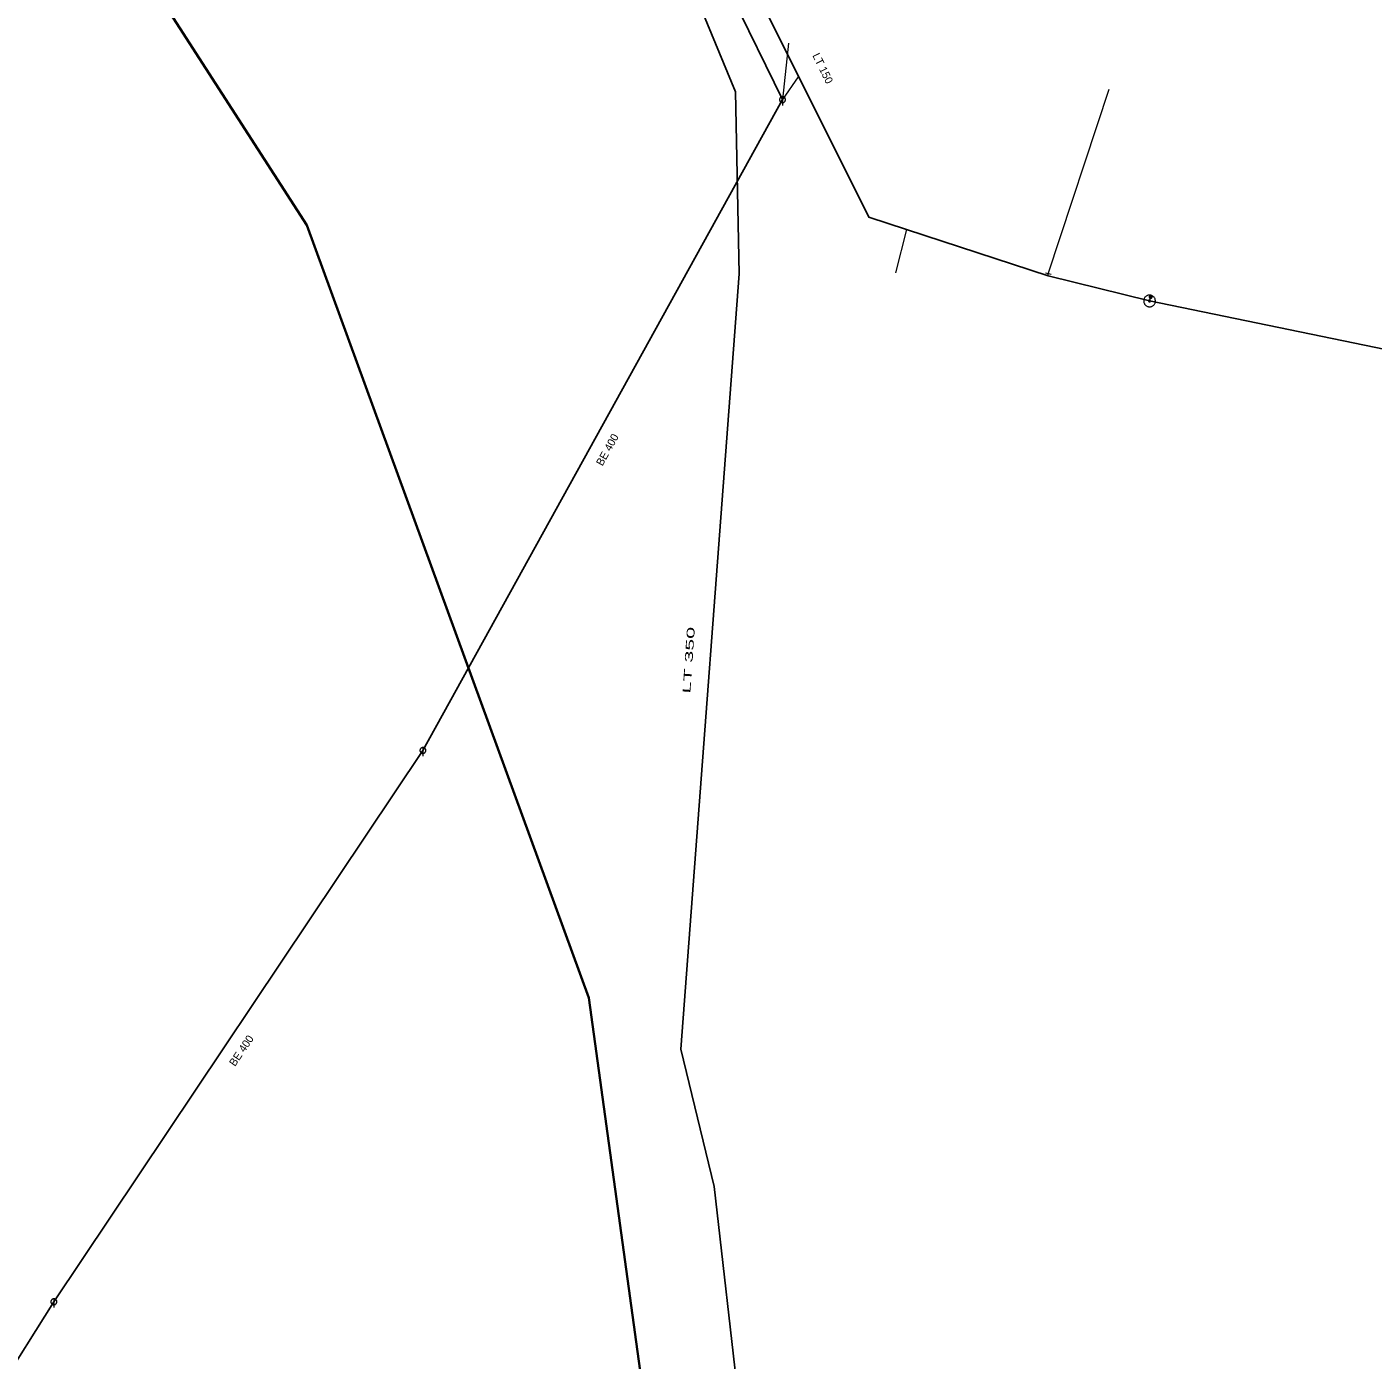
# Model space of a CAD drawing. Extents: x -687468 to -685917, y -974192 to -973456.
# Drawn here: x -686146.9 to -686032, y -973743.3 to -973629.5 of the extents above; entities that cross this region are included whole.
import ezdxf
from ezdxf.enums import TextEntityAlignment as Align

# ---------------------------------------------------------------- set-up
doc = ezdxf.new("R2010")
doc.units = 0
doc.header["$LTSCALE"] = 0.27
for name, color, linetype, lineweight in [('1', 7, 'Continuous', 13), ('11', 7, 'Continuous', 13), ('13', 7, 'Continuous', 13), ('14', 7, 'Continuous', 25), ('17', 7, 'Continuous', 25), ('22', 7, 'Continuous', 13), ('34', 7, 'Continuous', 13), ('47', 7, 'Continuous', 13), ('9', 7, 'Continuous', 13)]:
    doc.layers.add(name, color=color, linetype=linetype, lineweight=lineweight)

msp = doc.modelspace()

# ---------------------------------------------------------------- linework, layer by layer
at = {"layer": '11'}
for p in [(-686081.876, -973630.858), (-686081.043, -973633.743)]:
    msp.add_line(p, (-686082.39, -973635.68), dxfattribs=at)
at = {"layer": '13'}
for p, q in [((-686059.708, -973650.548), (-686054.519, -973634.795)), ((-686071.797, -973646.764), (-686072.73, -973650.474))]:
    msp.add_line(p, q, dxfattribs=at)
at = {"layer": '14'}
for p, q in [((-686098.62, -973602.51), (-686082.39, -973635.68)), ((-686082.39, -973635.68), (-686113.079, -973691.236)), ((-686113.079, -973691.236), (-686144.579, -973738.3)), ((-686144.579, -973738.3), (-686176.51, -973788.84))]:
    msp.add_line(p, q, dxfattribs=at)
at = {"layer": '14', "lineweight": 13}
for p, q in [((-686059.705, -973650.715), (-686059.708, -973650.548)), ((-686051.061, -973652.866), (-686050.965, -973652.512))]:
    msp.add_line(p, q, dxfattribs=at)
at = {"layer": '17', "lineweight": 35}
msp.add_lwpolyline([(-686160.425, -973551.891), (-686169.469, -973574.282), (-686122.999, -973646.384), (-686098.932, -973712.353), (-686089.329, -973782.048), (-686297.791, -974027.806), (-686326.807, -974076.614), (-686379.703, -974100.561), (-686411.584, -974111.413)], dxfattribs=at)
at = {"layer": '17'}
for points in [[(-686051.061, -973652.866), (-686059.705, -973650.715), (-686071.797, -973646.764), (-686075.022, -973645.71), (-686084.908, -973625.859)], [(-686089.459, -973627.585), (-686086.411, -973635.017), (-686086.079, -973650.552), (-686091.072, -973716.745), (-686088.221, -973728.447), (-686086.081, -973747.168), (-686087.506, -973758.201), (-686097.397, -973770.949)], [(-685917.086, -973739.927), (-685925.488, -973736.036), (-685936.592, -973728.633), (-685945.129, -973721.528), (-685963.855, -973704.352), (-685983.197, -973675.239), (-685998.767, -973663.649), (-686051.061, -973652.866)]]:
    msp.add_lwpolyline(points, dxfattribs=at)
at = {"layer": '22'}
for p, q in [((-686082.389, -973635.428), (-686082.39, -973636.172)), ((-686113.079, -973690.984), (-686113.08, -973691.728)), ((-686144.578, -973738.048), (-686144.579, -973738.792))]:
    msp.add_line(p, q, dxfattribs=at)
for points in [[(-686082.138, -973635.68), (-686082.139, -973635.654), (-686082.143, -973635.628), (-686082.149, -973635.602), (-686082.159, -973635.578), (-686082.171, -973635.554), (-686082.185, -973635.532), (-686082.202, -973635.511), (-686082.22, -973635.493), (-686082.241, -973635.476), (-686082.263, -973635.462), (-686082.287, -973635.45), (-686082.311, -973635.44), (-686082.337, -973635.434), (-686082.363, -973635.43), (-686082.389, -973635.428), (-686082.415, -973635.429), (-686082.441, -973635.433), (-686082.467, -973635.439), (-686082.492, -973635.449), (-686082.515, -973635.461), (-686082.537, -973635.475), (-686082.558, -973635.492), (-686082.576, -973635.51), (-686082.593, -973635.531), (-686082.607, -973635.553), (-686082.619, -973635.577), (-686082.629, -973635.601), (-686082.636, -973635.627), (-686082.64, -973635.653), (-686082.642, -973635.679), (-686082.641, -973635.705), (-686082.637, -973635.731), (-686082.63, -973635.757), (-686082.62, -973635.782), (-686082.608, -973635.805), (-686082.594, -973635.827), (-686082.577, -973635.848), (-686082.559, -973635.866), (-686082.538, -973635.883), (-686082.516, -973635.897), (-686082.493, -973635.909), (-686082.468, -973635.919), (-686082.442, -973635.926), (-686082.416, -973635.93), (-686082.39, -973635.932), (-686082.364, -973635.931), (-686082.338, -973635.927), (-686082.312, -973635.92), (-686082.288, -973635.91), (-686082.264, -973635.898), (-686082.242, -973635.884), (-686082.221, -973635.867), (-686082.203, -973635.849), (-686082.186, -973635.828), (-686082.172, -973635.806), (-686082.16, -973635.783), (-686082.15, -973635.758), (-686082.144, -973635.732), (-686082.14, -973635.706)], [(-686112.828, -973691.236), (-686112.829, -973691.21), (-686112.833, -973691.184), (-686112.839, -973691.158), (-686112.849, -973691.134), (-686112.861, -973691.11), (-686112.875, -973691.088), (-686112.892, -973691.067), (-686112.91, -973691.049), (-686112.931, -973691.032), (-686112.953, -973691.018), (-686112.977, -973691.006), (-686113.001, -973690.996), (-686113.027, -973690.99), (-686113.053, -973690.986), (-686113.079, -973690.984), (-686113.105, -973690.985), (-686113.131, -973690.989), (-686113.157, -973690.995), (-686113.182, -973691.005), (-686113.205, -973691.017), (-686113.227, -973691.031), (-686113.248, -973691.048), (-686113.266, -973691.066), (-686113.283, -973691.087), (-686113.297, -973691.109), (-686113.309, -973691.133), (-686113.319, -973691.157), (-686113.326, -973691.183), (-686113.33, -973691.209), (-686113.331, -973691.235), (-686113.331, -973691.261), (-686113.327, -973691.287), (-686113.32, -973691.313), (-686113.31, -973691.338), (-686113.298, -973691.361), (-686113.284, -973691.383), (-686113.267, -973691.404), (-686113.249, -973691.422), (-686113.228, -973691.439), (-686113.206, -973691.453), (-686113.183, -973691.465), (-686113.158, -973691.475), (-686113.132, -973691.482), (-686113.106, -973691.486), (-686113.08, -973691.488), (-686113.054, -973691.487), (-686113.028, -973691.483), (-686113.002, -973691.476), (-686112.978, -973691.466), (-686112.954, -973691.454), (-686112.932, -973691.44), (-686112.911, -973691.423), (-686112.893, -973691.405), (-686112.876, -973691.384), (-686112.862, -973691.362), (-686112.85, -973691.339), (-686112.84, -973691.314), (-686112.834, -973691.288), (-686112.83, -973691.262)], [(-686144.327, -973738.3), (-686144.328, -973738.274), (-686144.332, -973738.248), (-686144.338, -973738.222), (-686144.348, -973738.198), (-686144.36, -973738.174), (-686144.374, -973738.152), (-686144.391, -973738.131), (-686144.409, -973738.113), (-686144.43, -973738.096), (-686144.452, -973738.082), (-686144.476, -973738.07), (-686144.5, -973738.06), (-686144.526, -973738.054), (-686144.552, -973738.05), (-686144.578, -973738.048), (-686144.604, -973738.049), (-686144.63, -973738.053), (-686144.656, -973738.059), (-686144.681, -973738.069), (-686144.704, -973738.081), (-686144.726, -973738.095), (-686144.747, -973738.112), (-686144.765, -973738.13), (-686144.782, -973738.151), (-686144.796, -973738.173), (-686144.808, -973738.197), (-686144.818, -973738.221), (-686144.825, -973738.247), (-686144.829, -973738.273), (-686144.831, -973738.299), (-686144.83, -973738.325), (-686144.826, -973738.351), (-686144.819, -973738.377), (-686144.809, -973738.402), (-686144.797, -973738.425), (-686144.783, -973738.447), (-686144.766, -973738.468), (-686144.748, -973738.486), (-686144.727, -973738.503), (-686144.705, -973738.517), (-686144.682, -973738.529), (-686144.657, -973738.539), (-686144.631, -973738.546), (-686144.605, -973738.55), (-686144.579, -973738.552), (-686144.553, -973738.551), (-686144.527, -973738.547), (-686144.501, -973738.54), (-686144.477, -973738.53), (-686144.453, -973738.518), (-686144.431, -973738.504), (-686144.41, -973738.487), (-686144.392, -973738.469), (-686144.375, -973738.448), (-686144.361, -973738.426), (-686144.349, -973738.403), (-686144.339, -973738.378), (-686144.333, -973738.352), (-686144.329, -973738.326)]]:
    msp.add_lwpolyline(points, close=True, dxfattribs=at)
at = {"layer": '34'}
msp.add_line((-686059.466, -973650.604), (-686059.949, -973650.491), dxfattribs=at)
at = {"layer": '47'}
for points in [[(-686050.577, -973652.992), (-686050.567, -973652.941), (-686050.561, -973652.889), (-686050.562, -973652.837), (-686050.567, -973652.785), (-686050.578, -973652.733), (-686050.595, -973652.683), (-686050.617, -973652.636), (-686050.643, -973652.591), (-686050.674, -973652.549), (-686050.709, -973652.51), (-686050.748, -973652.475), (-686050.791, -973652.445), (-686050.836, -973652.419), (-686050.884, -973652.398), (-686050.934, -973652.382), (-686050.985, -973652.372), (-686051.037, -973652.366), (-686051.09, -973652.367), (-686051.141, -973652.372), (-686051.193, -973652.383), (-686051.243, -973652.4), (-686051.291, -973652.422), (-686051.336, -973652.448), (-686051.378, -973652.478), (-686051.416, -973652.514), (-686051.451, -973652.553), (-686051.482, -973652.596), (-686051.507, -973652.641), (-686051.528, -973652.689), (-686051.544, -973652.739), (-686051.554, -973652.79), (-686051.56, -973652.842), (-686051.56, -973652.895), (-686051.554, -973652.946), (-686051.543, -973652.998), (-686051.527, -973653.047), (-686051.505, -973653.095), (-686051.479, -973653.14), (-686051.448, -973653.183), (-686051.412, -973653.221), (-686051.373, -973653.256), (-686051.331, -973653.287), (-686051.285, -973653.312), (-686051.237, -973653.333), (-686051.187, -973653.349), (-686051.136, -973653.359), (-686051.084, -973653.365), (-686051.032, -973653.365), (-686050.98, -973653.359), (-686050.928, -973653.348), (-686050.879, -973653.332), (-686050.832, -973653.31), (-686050.787, -973653.284), (-686050.744, -973653.252), (-686050.705, -973653.217), (-686050.67, -973653.178), (-686050.64, -973653.136), (-686050.614, -973653.09), (-686050.593, -973653.042)], [(-686050.981, -973652.886), (-686050.979, -973652.878), (-686050.979, -973652.869), (-686050.979, -973652.861), (-686050.98, -973652.853), (-686050.981, -973652.844), (-686050.984, -973652.836), (-686050.988, -973652.828), (-686050.992, -973652.82), (-686050.997, -973652.814), (-686051.003, -973652.807), (-686051.01, -973652.801), (-686051.017, -973652.796), (-686051.024, -973652.792), (-686051.031, -973652.788), (-686051.04, -973652.786), (-686051.048, -973652.784), (-686051.057, -973652.784), (-686051.065, -973652.784), (-686051.073, -973652.785), (-686051.082, -973652.786), (-686051.09, -973652.789), (-686051.098, -973652.793), (-686051.106, -973652.797), (-686051.113, -973652.802), (-686051.119, -973652.808), (-686051.125, -973652.815), (-686051.13, -973652.822), (-686051.134, -973652.829), (-686051.138, -973652.836), (-686051.14, -973652.845), (-686051.142, -973652.853), (-686051.142, -973652.862), (-686051.142, -973652.87), (-686051.141, -973652.878), (-686051.14, -973652.887), (-686051.137, -973652.895), (-686051.133, -973652.903), (-686051.129, -973652.911), (-686051.124, -973652.918), (-686051.118, -973652.924), (-686051.111, -973652.93), (-686051.104, -973652.935), (-686051.097, -973652.939), (-686051.09, -973652.943), (-686051.081, -973652.945), (-686051.073, -973652.947), (-686051.064, -973652.947), (-686051.056, -973652.947), (-686051.048, -973652.946), (-686051.039, -973652.945), (-686051.031, -973652.942), (-686051.023, -973652.938), (-686051.015, -973652.934), (-686051.009, -973652.929), (-686051.002, -973652.923), (-686050.996, -973652.916), (-686050.991, -973652.909), (-686050.987, -973652.902), (-686050.983, -973652.895)]]:
    msp.add_lwpolyline(points, close=True, dxfattribs=at)
at = {"layer": '9'}
for points in [[(-686050.838, -973652.512), (-686050.84, -973652.499), (-686050.842, -973652.486), (-686050.845, -973652.473), (-686050.85, -973652.461), (-686050.855, -973652.449), (-686050.863, -973652.438), (-686050.87, -973652.428), (-686050.88, -973652.418), (-686050.891, -973652.41), (-686050.902, -973652.402), (-686050.914, -973652.397), (-686050.926, -973652.392), (-686050.939, -973652.389), (-686050.951, -973652.387), (-686050.965, -973652.386), (-686050.978, -973652.387), (-686050.99, -973652.389), (-686051.004, -973652.392), (-686051.016, -973652.397), (-686051.027, -973652.402), (-686051.039, -973652.41), (-686051.049, -973652.418), (-686051.059, -973652.428), (-686051.066, -973652.438), (-686051.074, -973652.449), (-686051.08, -973652.461), (-686051.085, -973652.473), (-686051.088, -973652.486), (-686051.09, -973652.499), (-686051.091, -973652.512), (-686051.09, -973652.525), (-686051.088, -973652.538), (-686051.085, -973652.551), (-686051.08, -973652.563), (-686051.074, -973652.575), (-686051.066, -973652.586), (-686051.059, -973652.596), (-686051.049, -973652.606), (-686051.039, -973652.614), (-686051.027, -973652.621), (-686051.016, -973652.627), (-686051.004, -973652.632), (-686050.99, -973652.635), (-686050.978, -973652.637), (-686050.965, -973652.638), (-686050.951, -973652.637), (-686050.939, -973652.635), (-686050.926, -973652.632), (-686050.914, -973652.627), (-686050.902, -973652.621), (-686050.891, -973652.614), (-686050.88, -973652.606), (-686050.87, -973652.596), (-686050.863, -973652.586), (-686050.855, -973652.575), (-686050.85, -973652.563), (-686050.845, -973652.551), (-686050.842, -973652.538), (-686050.84, -973652.525)], [(-686050.858, -973652.512), (-686050.858, -973652.5), (-686050.86, -973652.49), (-686050.864, -973652.478), (-686050.868, -973652.469), (-686050.873, -973652.459), (-686050.879, -973652.45), (-686050.886, -973652.441), (-686050.894, -973652.433), (-686050.902, -973652.426), (-686050.912, -973652.42), (-686050.922, -973652.415), (-686050.931, -973652.411), (-686050.943, -973652.407), (-686050.953, -973652.406), (-686050.965, -973652.406), (-686050.976, -973652.406), (-686050.987, -973652.407), (-686050.998, -973652.411), (-686051.007, -973652.415), (-686051.017, -973652.42), (-686051.027, -973652.426), (-686051.036, -973652.433), (-686051.044, -973652.441), (-686051.051, -973652.45), (-686051.056, -973652.459), (-686051.061, -973652.469), (-686051.066, -973652.478), (-686051.069, -973652.49), (-686051.071, -973652.5), (-686051.071, -973652.512), (-686051.071, -973652.523), (-686051.069, -973652.534), (-686051.066, -973652.545), (-686051.061, -973652.554), (-686051.056, -973652.565), (-686051.051, -973652.574), (-686051.044, -973652.583), (-686051.036, -973652.591), (-686051.027, -973652.598), (-686051.017, -973652.603), (-686051.007, -973652.608), (-686050.998, -973652.613), (-686050.987, -973652.616), (-686050.976, -973652.618), (-686050.965, -973652.618), (-686050.953, -973652.618), (-686050.943, -973652.616), (-686050.931, -973652.613), (-686050.922, -973652.608), (-686050.912, -973652.603), (-686050.902, -973652.598), (-686050.894, -973652.591), (-686050.886, -973652.583), (-686050.879, -973652.574), (-686050.873, -973652.565), (-686050.868, -973652.554), (-686050.864, -973652.545), (-686050.86, -973652.534), (-686050.858, -973652.523)], [(-686050.877, -973652.512), (-686050.879, -973652.503), (-686050.88, -973652.494), (-686050.882, -973652.485), (-686050.886, -973652.477), (-686050.89, -973652.469), (-686050.895, -973652.461), (-686050.901, -973652.454), (-686050.907, -973652.448), (-686050.914, -973652.442), (-686050.922, -973652.437), (-686050.929, -973652.433), (-686050.938, -973652.429), (-686050.946, -973652.427), (-686050.956, -973652.426), (-686050.965, -973652.424), (-686050.973, -973652.426), (-686050.983, -973652.427), (-686050.992, -973652.429), (-686051, -973652.433), (-686051.007, -973652.437), (-686051.016, -973652.442), (-686051.022, -973652.448), (-686051.029, -973652.454), (-686051.034, -973652.461), (-686051.039, -973652.469), (-686051.044, -973652.477), (-686051.047, -973652.485), (-686051.049, -973652.494), (-686051.051, -973652.503), (-686051.052, -973652.512), (-686051.051, -973652.521), (-686051.049, -973652.53), (-686051.047, -973652.539), (-686051.044, -973652.547), (-686051.039, -973652.554), (-686051.034, -973652.563), (-686051.029, -973652.57), (-686051.022, -973652.576), (-686051.016, -973652.581), (-686051.007, -973652.587), (-686051, -973652.591), (-686050.992, -973652.594), (-686050.983, -973652.597), (-686050.973, -973652.598), (-686050.965, -973652.599), (-686050.956, -973652.598), (-686050.946, -973652.597), (-686050.938, -973652.594), (-686050.929, -973652.591), (-686050.922, -973652.587), (-686050.914, -973652.581), (-686050.907, -973652.576), (-686050.901, -973652.57), (-686050.895, -973652.563), (-686050.89, -973652.554), (-686050.886, -973652.547), (-686050.882, -973652.539), (-686050.88, -973652.53), (-686050.879, -973652.521)], [(-686050.897, -973652.512), (-686050.897, -973652.505), (-686050.9, -973652.498), (-686050.901, -973652.491), (-686050.904, -973652.485), (-686050.907, -973652.478), (-686050.911, -973652.473), (-686050.914, -973652.467), (-686050.919, -973652.462), (-686050.926, -973652.458), (-686050.931, -973652.454), (-686050.938, -973652.451), (-686050.944, -973652.448), (-686050.951, -973652.447), (-686050.958, -973652.445), (-686050.965, -973652.445), (-686050.972, -973652.445), (-686050.978, -973652.447), (-686050.985, -973652.448), (-686050.992, -973652.451), (-686050.999, -973652.454), (-686051.004, -973652.458), (-686051.01, -973652.462), (-686051.015, -973652.467), (-686051.019, -973652.473), (-686051.022, -973652.478), (-686051.026, -973652.485), (-686051.029, -973652.491), (-686051.031, -973652.498), (-686051.032, -973652.505), (-686051.032, -973652.512), (-686051.032, -973652.519), (-686051.031, -973652.526), (-686051.029, -973652.532), (-686051.026, -973652.539), (-686051.022, -973652.546), (-686051.019, -973652.551), (-686051.015, -973652.557), (-686051.01, -973652.562), (-686051.004, -973652.566), (-686050.999, -973652.57), (-686050.992, -973652.573), (-686050.985, -973652.576), (-686050.978, -973652.578), (-686050.972, -973652.579), (-686050.965, -973652.579), (-686050.958, -973652.579), (-686050.951, -973652.578), (-686050.944, -973652.576), (-686050.938, -973652.573), (-686050.931, -973652.57), (-686050.926, -973652.566), (-686050.919, -973652.562), (-686050.914, -973652.557), (-686050.911, -973652.551), (-686050.907, -973652.546), (-686050.904, -973652.539), (-686050.901, -973652.532), (-686050.9, -973652.526), (-686050.897, -973652.519)], [(-686050.918, -973652.512), (-686050.918, -973652.507), (-686050.919, -973652.502), (-686050.919, -973652.497), (-686050.922, -973652.493), (-686050.924, -973652.488), (-686050.927, -973652.483), (-686050.929, -973652.481), (-686050.934, -973652.477), (-686050.936, -973652.474), (-686050.941, -973652.471), (-686050.946, -973652.469), (-686050.95, -973652.467), (-686050.955, -973652.466), (-686050.96, -973652.465), (-686050.965, -973652.465), (-686050.97, -973652.465), (-686050.975, -973652.466), (-686050.98, -973652.467), (-686050.983, -973652.469), (-686050.989, -973652.471), (-686050.993, -973652.474), (-686050.997, -973652.477), (-686051, -973652.481), (-686051.002, -973652.483), (-686051.005, -973652.488), (-686051.007, -973652.493), (-686051.01, -973652.497), (-686051.011, -973652.502), (-686051.012, -973652.507), (-686051.012, -973652.512), (-686051.012, -973652.517), (-686051.011, -973652.522), (-686051.01, -973652.527), (-686051.007, -973652.531), (-686051.005, -973652.536), (-686051.002, -973652.54), (-686051, -973652.544), (-686050.997, -973652.547), (-686050.993, -973652.549), (-686050.989, -973652.553), (-686050.983, -973652.554), (-686050.98, -973652.557), (-686050.975, -973652.558), (-686050.97, -973652.559), (-686050.965, -973652.559), (-686050.96, -973652.559), (-686050.955, -973652.558), (-686050.95, -973652.557), (-686050.946, -973652.554), (-686050.941, -973652.553), (-686050.936, -973652.549), (-686050.934, -973652.547), (-686050.929, -973652.544), (-686050.927, -973652.54), (-686050.924, -973652.536), (-686050.922, -973652.531), (-686050.919, -973652.527), (-686050.919, -973652.522), (-686050.918, -973652.517)], [(-686050.938, -973652.512), (-686050.938, -973652.509), (-686050.938, -973652.505), (-686050.939, -973652.504), (-686050.94, -973652.5), (-686050.941, -973652.498), (-686050.943, -973652.496), (-686050.945, -973652.494), (-686050.946, -973652.492), (-686050.949, -973652.49), (-686050.951, -973652.488), (-686050.953, -973652.487), (-686050.956, -973652.486), (-686050.958, -973652.485), (-686050.962, -973652.485), (-686050.965, -973652.485), (-686050.968, -973652.485), (-686050.971, -973652.485), (-686050.973, -973652.486), (-686050.976, -973652.487), (-686050.978, -973652.488), (-686050.98, -973652.49), (-686050.983, -973652.492), (-686050.985, -973652.494), (-686050.987, -973652.496), (-686050.989, -973652.498), (-686050.99, -973652.5), (-686050.99, -973652.504), (-686050.992, -973652.505), (-686050.992, -973652.509), (-686050.993, -973652.512), (-686050.992, -973652.515), (-686050.992, -973652.518), (-686050.99, -973652.521), (-686050.99, -973652.523), (-686050.989, -973652.526), (-686050.987, -973652.527), (-686050.985, -973652.531), (-686050.983, -973652.532), (-686050.98, -973652.534), (-686050.978, -973652.536), (-686050.976, -973652.537), (-686050.973, -973652.538), (-686050.971, -973652.539), (-686050.968, -973652.539), (-686050.965, -973652.54), (-686050.962, -973652.539), (-686050.958, -973652.539), (-686050.956, -973652.538), (-686050.953, -973652.537), (-686050.951, -973652.536), (-686050.949, -973652.534), (-686050.946, -973652.532), (-686050.945, -973652.531), (-686050.943, -973652.527), (-686050.941, -973652.526), (-686050.94, -973652.523), (-686050.939, -973652.521), (-686050.938, -973652.518), (-686050.938, -973652.515)], [(-686050.956, -973652.512), (-686050.956, -973652.511), (-686050.956, -973652.51), (-686050.958, -973652.51), (-686050.958, -973652.509), (-686050.958, -973652.508), (-686050.958, -973652.507), (-686050.958, -973652.507), (-686050.96, -973652.505), (-686050.96, -973652.505), (-686050.961, -973652.505), (-686050.962, -973652.505), (-686050.963, -973652.505), (-686050.963, -973652.504), (-686050.963, -973652.504), (-686050.965, -973652.504), (-686050.966, -973652.504), (-686050.967, -973652.504), (-686050.967, -973652.505), (-686050.968, -973652.505), (-686050.968, -973652.505), (-686050.97, -973652.505), (-686050.97, -973652.505), (-686050.971, -973652.507), (-686050.971, -973652.507), (-686050.972, -973652.508), (-686050.972, -973652.509), (-686050.973, -973652.51), (-686050.973, -973652.51), (-686050.973, -973652.511), (-686050.973, -973652.512), (-686050.973, -973652.513), (-686050.973, -973652.514), (-686050.973, -973652.514), (-686050.972, -973652.515), (-686050.972, -973652.516), (-686050.971, -973652.517), (-686050.971, -973652.517), (-686050.97, -973652.518), (-686050.97, -973652.518), (-686050.968, -973652.519), (-686050.968, -973652.519), (-686050.967, -973652.52), (-686050.967, -973652.52), (-686050.966, -973652.52), (-686050.965, -973652.52), (-686050.963, -973652.52), (-686050.963, -973652.52), (-686050.963, -973652.52), (-686050.962, -973652.519), (-686050.961, -973652.519), (-686050.96, -973652.518), (-686050.96, -973652.518), (-686050.958, -973652.517), (-686050.958, -973652.517), (-686050.958, -973652.516), (-686050.958, -973652.515), (-686050.958, -973652.514), (-686050.956, -973652.514), (-686050.956, -973652.513)]]:
    msp.add_lwpolyline(points, close=True, dxfattribs=at)

# ---------------------------------------------------------------- texts
at = {"layer": '1'}
for s, rotation, p in [('LT 150', 296, (-686079.247, -973633.15)), ('BE 400', 61, (-686097.049, -973665.725)), ('BE 400', 56, (-686128.301, -973717.045))]:
    msp.add_text(s, height=0.6667, rotation=rotation, dxfattribs=at).set_placement(p, align=Align.CENTER)
at = {"layer": '1', "width": 2.05}
msp.add_text('LT 350', height=0.6667, rotation=86, dxfattribs=at).set_placement((-686090.062, -973683.551), align=Align.CENTER)

doc.saveas('drawing.dxf')
